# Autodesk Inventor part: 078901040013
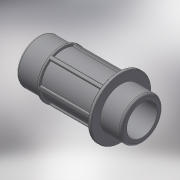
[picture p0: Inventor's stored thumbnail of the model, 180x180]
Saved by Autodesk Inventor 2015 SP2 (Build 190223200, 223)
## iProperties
Created: 2018-02
Part Number: 078901040013
Material: Generic
Description: PLASSON THREADED MALE ADAPTOR 40-1.1/4"
Document SubType Name: Modeling
Designer: KIM
Density: 1 g/cm^3
Appearance: Default
Author: KIM
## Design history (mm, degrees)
derived "078901.ipt"
feature "Solid1::078901.ipt"
tag "TaggingFeature1"
body "Solid1"
other parameters: "d4" = 2.0955, "d14" = 3.3528, "d15" = 1.6764, "d17" = 0, "d20" = 360 deg, "d40" = 22, "d41" = 41.91, "d45" = 46.101, "d46" = 29.337, "d47" = 2.2, "d85" = 0.4191, "d103" = 23, "d104" = 58, "d105" = 0.4191, "R_" = 41.91, "E_" = 58, "l_2" = 22
